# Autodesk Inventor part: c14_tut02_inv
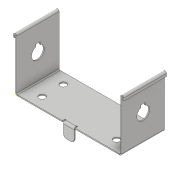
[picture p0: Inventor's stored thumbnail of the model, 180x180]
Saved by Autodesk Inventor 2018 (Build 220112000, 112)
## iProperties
Created: 2015-06
Part Number: c14_tut02_inv
Material: Generic
Document SubType Name: Sheet Metal
Designer: Sandeep
Density: 1 g/cm^3
Sheet Metal Rule: Default_mm
Appearance: Default
Flat Pattern Width: 5.12619 cm
Flat Pattern Length: 20.443 cm
Flat Pattern Area: 104.795 cm^2
Sheet Metal Width: 51.262 mm
Sheet Metal Length: 204.430 mm
Sheet Metal Area: 10479.484 mm^2
Author: Sandeep
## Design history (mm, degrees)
sketch "Sketch1"
  geometry: 1 further point
node "Face1"
  sketch "Sketch2"
    geometry: L1 (0, 0)-(100, 0); L2 (100, 0)-(100, 40); L3 (100, 40)-(0, 40); L4 (0, 40)-(0, 0)
    constraints: 8 end point, 2 parallel, 1 horizontal, 1 perpendicular
    dimensions: "d0" = 100 distance between parallel lines of L2 L4; "d1" = 40 distance between parallel lines of L1 L3
hole "Hole1" diameter "d5" = 6; stored, may be unused: countersink angle "d9" = 90 deg, drill point angle "d11" = 118 deg; dims "d3" = 10, "d4" = 15, "d6" = 6, "d7" = 4, "d8" = 2, "d10" = 1 (= Thickness)
pattern_linear "Rectangular Pattern1" dims "d14" = 20
pattern_linear "Rectangular Pattern2" dims "d17" = 70
node "Flange1"
node "Flange2"
feature "Hem1" dims "d38" = 1 (= BendReliefWidth), "d39" = 0.5 (= BendReliefDepth), "d40" = 2 (= MinimumRemnant), "d41" = 1 (= BendRadius), "d42" = 4 (= 4 x Thickness), "d43" = 1 (= Thickness), "d44" = 0.5 (= 0.5 x d43), "d82" = 1 (= Thickness), "SeamGap" = 0.01
feature "Hem2" dims "d45" = 1 (= BendReliefWidth), "d46" = 0.5 (= BendReliefDepth), "d47" = 2 (= MinimumRemnant), "d48" = 1 (= BendRadius), "d49" = 4 (= 4 x Thickness), "d50" = 1 (= Thickness), "d51" = 0.5 (= 0.5 x d50), "d82" = 1 (= Thickness), "SeamGap" = 0.01
sketch "Sketch7"
  geometry: L1 (0, 40)-(0, 0) reference; L2 (48, 0)-(0, 0) reference; 2 further points
  dimensions: "d52" = 25 distance from line of point (25, 20) L1; "d53" = 20 distance from line of L2 point (25, 20)
feature "iFeature15:1" sketch "Sketch7"
sketch "Sketch8"
  geometry: L1 (17.2, 18)-(17.2, 22) reference; L2 (19.343, 18)-(17.2, 18) reference; L3 (17.2, 22)-(19.343, 22) reference; L4 (17.2, 18)-(17.2, 22) reference; L5 (17.2, 22)-(19.343, 22) reference; L6 (19.343, 18)-(17.2, 18) reference; L7 (48, 0)-(48, 40) reference; L8 (48, 40)-(1.5, 40) reference; L9 (48, 0)-(1.5, 0) reference; L10 (1.5, 40)-(1.5, 0) reference; A1 r 6 centre (25, 20) between (19.343, 18) and (19.343, 22) reference; A2 r 6 centre (25, 20) between (19.343, 18) and (19.343, 22) reference; 1 further point
  node "Projected Loop1"
node "Flange3"
feature "Corner Round1" dims "d78" = 3
workplane "Work Plane1"
mirror "Mirror1"
body "Solid1"
face "Plate1" dims "d82" = 1 (= Thickness)
sketch "Sketch3"
  geometry: L1 through (20, 0) direction (-1, 0); L2 through (0, -25) direction (0, -1); L3 (0, -50)-(40, -50); L4 (40, -50)-(40, 0)
  constraints: 6 end point, 1 horizontal, 1 perpendicular, 1 vertical
face "Plate2" dims "d18" = 1 (= BendReliefWidth), "d19" = 0.5 (= BendReliefDepth), "d20" = 2 (= MinimumRemnant), "d21" = 1 (= BendRadius), "d22" = 50, "d23" = 90 deg, "d24" = 1 (= BendRadius), "d25" = 4 (= CornerReliefSize), "d26" = 1 (= GapSize), "d27" = 1 (= JacobiRadiusSize), "d82" = 1 (= Thickness), "SeamGap" = 0.01
bend "Bend1" dims "d18" = 1 (= BendReliefWidth), "d19" = 0.5 (= BendReliefDepth), "d20" = 2 (= MinimumRemnant), "d21" = 1 (= BendRadius), "d22" = 50, "d23" = 90 deg, "d24" = 1 (= BendRadius), "d82" = 1 (= Thickness), "SeamGap" = 0.01
feature "Corner1" dims "d22" = 50, "d23" = 90 deg, "d25" = 4 (= CornerReliefSize), "d26" = 1 (= GapSize), "d27" = 1 (= JacobiRadiusSize)
sketch "Sketch4"
  geometry: L1 through (20, 0) direction (-1, 5.47e-48); L2 through (0, -25) direction (-2.71e-32, -1); L3 (0, -50)-(40, -50); L4 (40, -50)-(40, 0)
  constraints: 6 end point, 1 horizontal, 1 perpendicular, 1 vertical
face "Plate3" dims "d28" = 1 (= BendReliefWidth), "d29" = 0.5 (= BendReliefDepth), "d30" = 2 (= MinimumRemnant), "d31" = 1 (= BendRadius), "d32" = 50, "d33" = 90 deg, "d34" = 1 (= BendRadius), "d35" = 4 (= CornerReliefSize), "d36" = 1 (= GapSize), "d37" = 1 (= JacobiRadiusSize), "d82" = 1 (= Thickness), "SeamGap" = 0.01
bend "Bend2" dims "d28" = 1 (= BendReliefWidth), "d29" = 0.5 (= BendReliefDepth), "d30" = 2 (= MinimumRemnant), "d31" = 1 (= BendRadius), "d32" = 50, "d33" = 90 deg, "d34" = 1 (= BendRadius), "d82" = 1 (= Thickness), "SeamGap" = 0.01
feature "Corner2" dims "d32" = 50, "d33" = 90 deg, "d35" = 4 (= CornerReliefSize), "d36" = 1 (= GapSize), "d37" = 1 (= JacobiRadiusSize)
sketch "Sketch9"
  geometry: L1 (-53, 0)-(-43, 0); L2 (-43, 0)-(-43, 13); L3 (-43, 13)-(-53, 13); L4 (-53, 13)-(-53, 0)
  constraints: 8 end point
face "Plate4" dims "d67" = 1 (= BendReliefWidth), "d68" = 0.5 (= BendReliefDepth), "d69" = 2 (= MinimumRemnant), "d70" = 1 (= BendRadius), "d71" = 10, "d72" = 13, "d73" = 90 deg, "d74" = 1 (= BendRadius), "d75" = 4 (= CornerReliefSize), "d76" = 1 (= GapSize), "d77" = 1 (= JacobiRadiusSize), "d82" = 1 (= Thickness), "SeamGap" = 0.01
bend "Bend3" dims "d67" = 1 (= BendReliefWidth), "d68" = 0.5 (= BendReliefDepth), "d69" = 2 (= MinimumRemnant), "d70" = 1 (= BendRadius), "d72" = 13, "d73" = 90 deg, "d74" = 1 (= BendRadius), "d82" = 1 (= Thickness), "SeamGap" = 0.01
feature "Corner3" dims "d72" = 13, "d73" = 90 deg, "d75" = 4 (= CornerReliefSize), "d76" = 1 (= GapSize), "d77" = 1 (= JacobiRadiusSize)
sketch "Sketch5"
  geometry: L1 (1, 0)-(0, 0); L2 (-1, 0)-(-1, -2.5); L3 (-1, -2.5)-(-2, -2.5); L4 (-2, -2.5)-(-2, 0); A1 r 0.5 centre (-0.5, 0) between (0, 0) and (-1, 0); A2 r 1.5 centre (-0.5, 0) between (1, 0) and (-2, 0); 2 further points
  constraints: 8 end point, 4 point on circle
sketch "Sketch6"
  geometry: L1 (0, 0)-(1, 0); L2 (2, 0)-(2, -2.5); L3 (2, -2.5)-(3, -2.5); L4 (3, -2.5)-(3, 0); A1 r 0.5 centre (1.5, 0) between (2, 0) and (1, 0); A2 r 1.5 centre (1.5, 0) between (3, 0) and (0, 0); 2 further points
  constraints: 8 end point, 4 point on circle
feature "Definition1"
other parameters: "Thickness" = 1 (derived), "BendRadius" = 1 (= Thickness), "BendReliefWidth" = 1 (= Thickness), "BendReliefDepth" = 0.5 (= 0.5 x Thickness), "CornerReliefSize" = 4 (= 4 x Thickness), "MinimumRemnant" = 2 (= 2 x Thickness), "TransitionRadius" = 1 (= BendRadius), "JacobiRadiusSize" = 1 (= BendRadius), "GapSize" = 1 (= Thickness), "d2" = 1 (= BendRadius), "d81" = 90 deg, "BendRadius" = 1, "BendReliefDepth" = 0.5, "BendReliefWidth" = 1, "CornerReliefSize" = 4, "GapSize" = 1, "JacobiRadiusSize" = 1, "MinimumRemnant" = 2, "Thickness" = 1, "TransitionRadius" = 1
